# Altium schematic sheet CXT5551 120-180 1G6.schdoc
size 127 x 101 mm
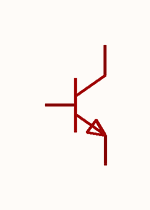
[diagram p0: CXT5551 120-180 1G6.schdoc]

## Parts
Q?  cxt5551(range:120-180)_c24259  [SOT-89-3_L4.5-W2.5-P1.50-LS4.2-BR]  (value not drawn)

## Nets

Not connected (* = marked no-connect by the designer): Q? 1(B) 2(C) 3(E)

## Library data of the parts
Q? = cxt5551(range:120-180)_c24259: 晶体管类型:NPN;集电极电流(Ic):600mA;集射极击穿电压(Vceo):160V;耗散功率(Pd):500mW;直流电流增益(hFE):120;; Manufacturer: CJ(江苏长电/长晶); Symbol: CXT5551 120-180 1G6; AddInBom: yes; ModelId: 6db690b7897d4d18a30d90c1b89525ee; ModelName: SOT-89-3_L4.3-W2.5-H1.6-LS4.1-P1.50; ModelTransform: 161.417,169.291,0,180,0,0,-18.661,0,0; type: NPN; Current - Collector(Ic): 600mA; Collector - Emitter Voltage VCEO: 160V; Pd - Power Dissipation: 500mW; DC Current Gain: 120; Transition frequency(fT): 100MHz; Current - Collector Cutoff: 50nA; Vce Saturation(VCE(sat)): 200mV; Emitter-Base Voltage(Vebo): 6V; Number: 1个NPN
